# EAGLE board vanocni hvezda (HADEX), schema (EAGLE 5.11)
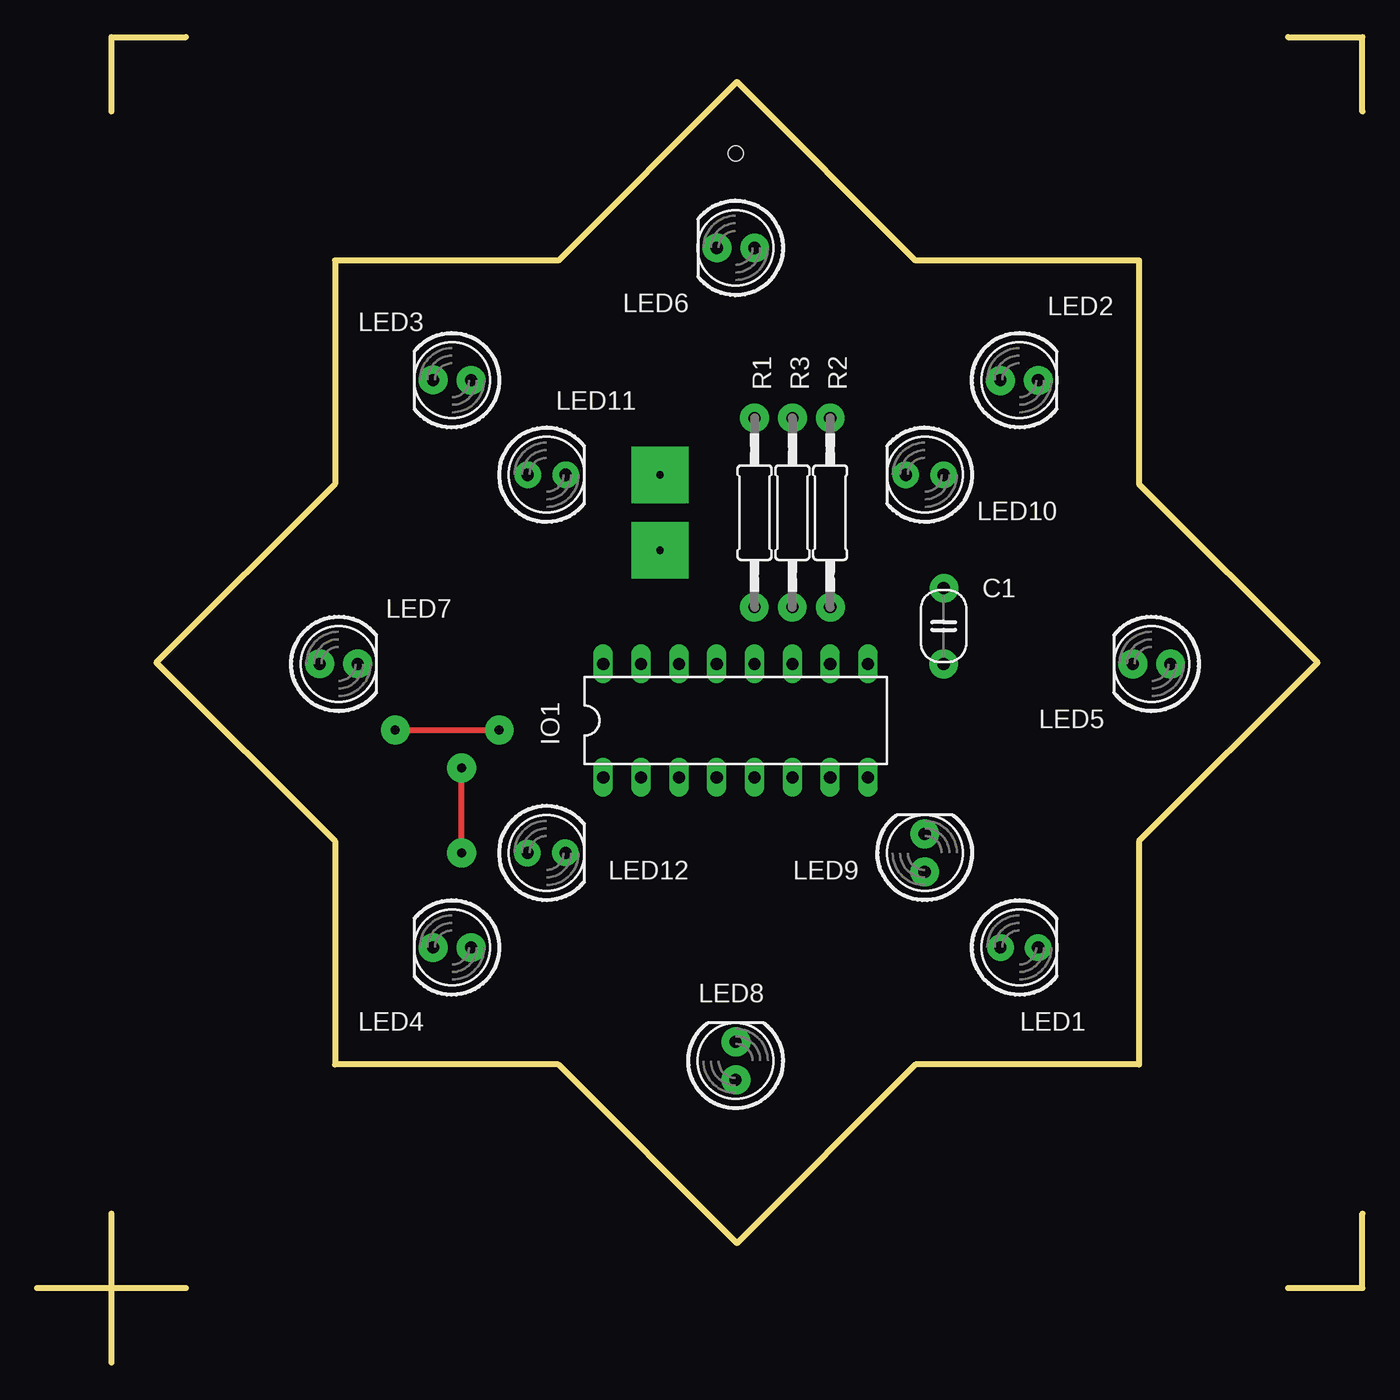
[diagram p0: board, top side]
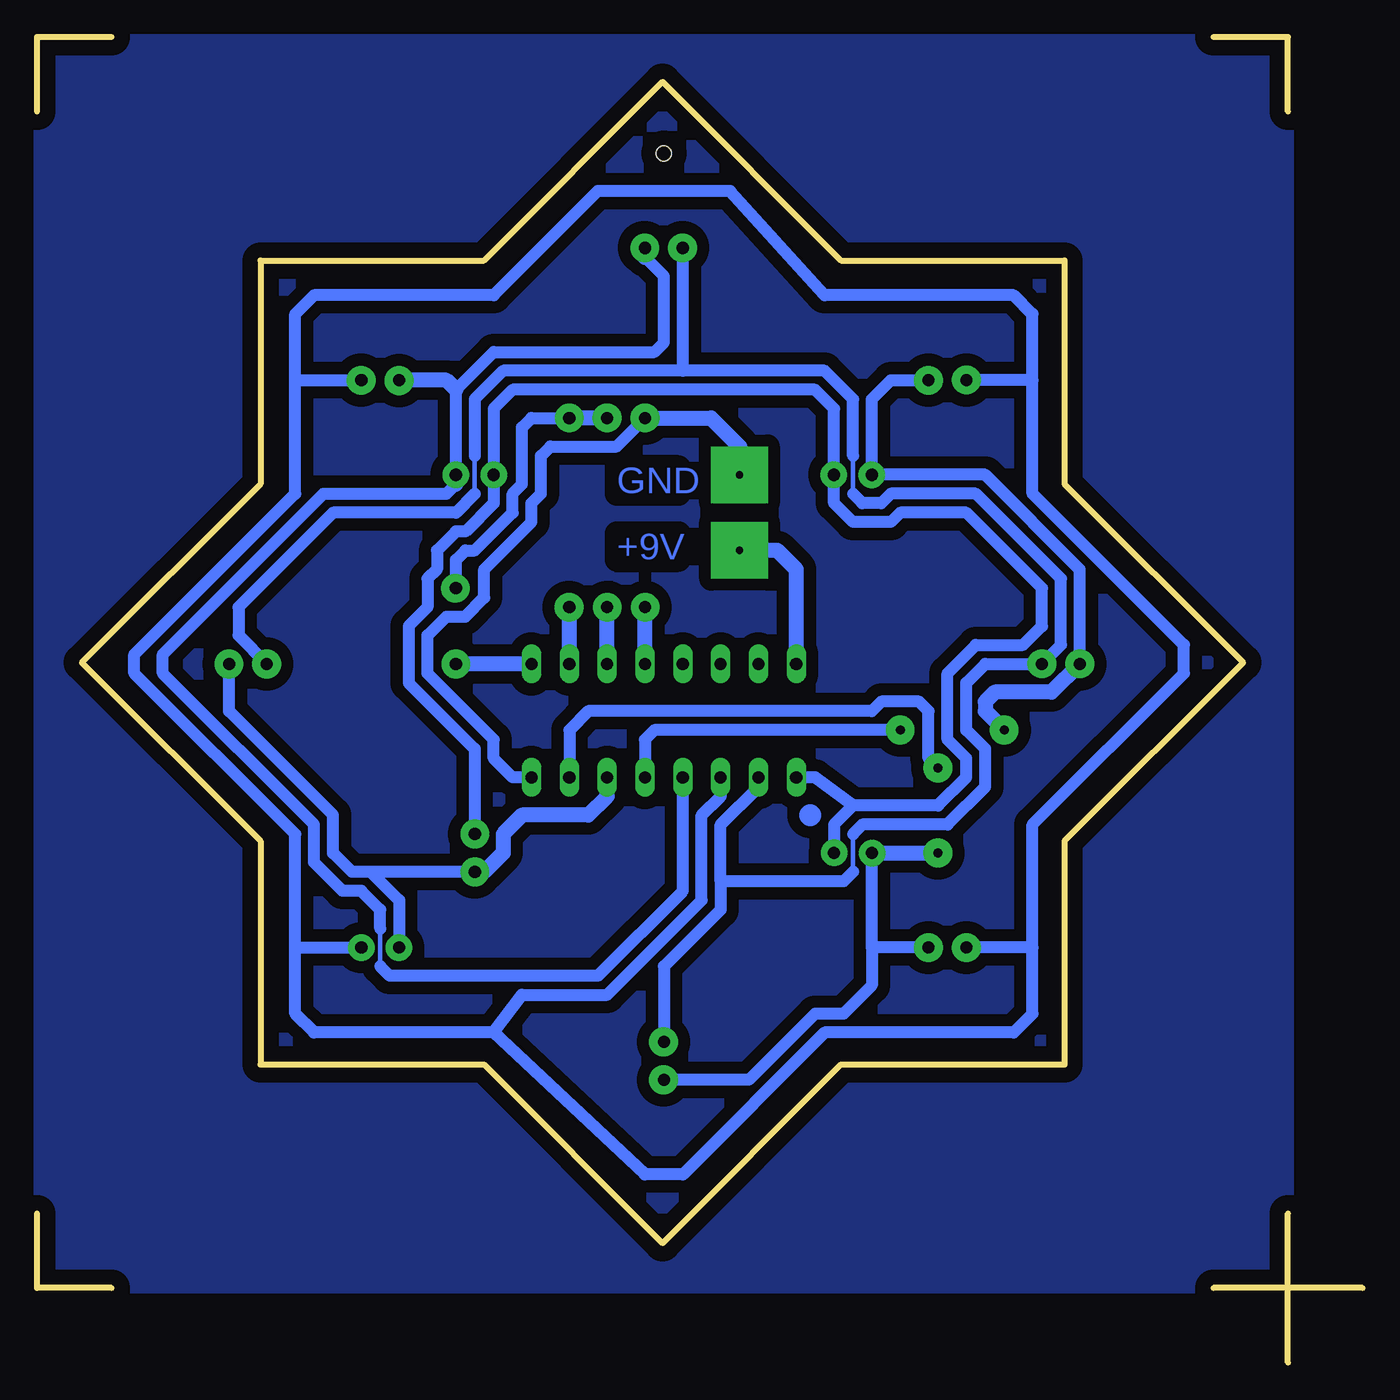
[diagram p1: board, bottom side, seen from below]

Size 89 x 89 mm. Coordinates in mm from the lower left corner, seen from the top.
Outline: 0,5 10,5
Outline: 5,0 5,10
Outline: 10,89 5,89 5,84
Outline: 84,89 89,89 89,84
Outline: 89,10 89,5 84,5
Outline: 59,20 47,8 35,20 20,20 20,35 8,47 20,59 20,74 35,74 47,86 59,74 74,74 74,59 86,47 74,35 74,20 59,20
Copper layers (1*16): Top 0.035mm / dielectric 1.5mm / Bottom 0.035mm
Design rules "default": minimum track width 10mil, minimum drill 24mil, track to track 8mil, track to pad 8mil, pad to pad 8mil, via to via 8mil, smd to smd 8mil, copper to edge 40mil, drill to drill 8mil, minimum pad ring 10mil, minimum via ring 8mil, stop-mask expansion 4mil, vias tented up to drill 0mil, thermal gap 10mil
Holes 1 mm at 46.91,81.2

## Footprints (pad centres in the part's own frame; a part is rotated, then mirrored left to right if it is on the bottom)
C3X5 = drill 0.813 pad 1.422 octagon: 1 -2.54,0; 2 2.54,0
DIL16 = drill 0.813 long: 1 -8.89,-3.81; 2 -6.35,-3.81; 3 -3.81,-3.81; 4 -1.27,-3.81; 5 1.27,-3.81; 6 3.81,-3.81; 7 6.35,-3.81; 8 8.89,-3.81; 9 8.89,3.81; 10 6.35,3.81; 11 3.81,3.81; 12 1.27,3.81; 13 -1.27,3.81; 14 -3.81,3.81; 15 -6.35,3.81; 16 -8.89,3.81
LED5MM = drill 0.813 octagon: A -1.27,0; K 1.27,0
0207/12 = drill 0.813 octagon: 1 -6.35,0; 2 6.35,0

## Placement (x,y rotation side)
C1  [C3X5]  60.88,49.45 90 top
IO1  [DIL16]  46.91,43.1 0 top
LED1  [LED5MM]  65.96,27.86 0 top
LED2  [LED5MM]  65.96,65.96 0 top
LED3  [LED5MM]  27.86,65.96 180 top
LED4  [LED5MM]  27.86,27.86 180 top
LED5  [LED5MM]  74.85,46.91 180 top
LED6  [LED5MM]  46.91,74.85 180 top
LED7  [LED5MM]  20.24,46.91 0 top
LED8  [LED5MM]  46.91,20.24 90 top
LED9  [LED5MM]  59.61,34.21 90 top
LED10  [LED5MM]  59.61,59.61 180 top
LED11  [LED5MM]  34.21,59.61 0 top
LED12  [LED5MM]  34.21,34.21 0 top
R1  [0207/12]  48.18,57.07 90 top
R2  [0207/12]  53.26,57.07 90 top
R3  [0207/12]  50.72,57.07 90 top

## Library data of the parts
C1 = kondenzatory
IO1 = 40xx
LED1-LED12 = LED diody
R1-R3 = rezistory

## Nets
S$1: LED3.A LED7.A LED11.A
S$4: IO1.12 R1.1
S$5: IO1.11 R3.1
S$6: IO1.10 R2.1
S$7: C1.1 IO1.9
S$8: IO1.16
S$9: LED2.A LED6.A LED10.A
S$10: IO1.5
S$13: IO1.7 LED4.A LED8.A LED12.A
S$14: IO1.3 LED1.K LED2.K LED3.K LED4.K
S$17: LED1.A LED5.A LED9.A
S$19: IO1.8 R1.2
S$21: LED5.K LED6.K LED7.K LED8.K
S$22: R2.2 R3.2
S$23: IO1.1 LED9.K LED10.K LED11.K LED12.K
S$24: C1.2

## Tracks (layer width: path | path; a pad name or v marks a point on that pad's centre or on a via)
S$1  (via drill 0.6 pad 1.93)
  Top 0.406: v24.05,42.47 v31.04,42.47
  Bottom 0.813: LED3.A 31.67,65.96 32.94,64.69 LED11.A 25.32,59.61 18.97,53.26 LED7.A
  Bottom 1.016: LED7.A 20.88,45.01 24.68,45.01 25.32,44.37 25.32,43.73 v24.05,42.47
S$2
  Bottom 0.813: 45.64,38.66 45.64,31.67 51.35,25.95 65.33,25.95 65.96,26.59
S$3  (via drill 0.5 pad 1.93)
  other vias: 48.17,50.71
S$4
  Bottom 1.016: IO1.12 R1.1
S$5
  Bottom 1.016: IO1.11 R3.1
S$6
  Bottom 1.016: IO1.10 R2.1
S$7
  Bottom 1.016: IO1.9 C1.1
S$8  (via drill 0.5 pad 3.81)
  Bottom 1.016: IO1.16 38.02,53.26 39.29,54.53 v41.83,54.53
S$9
  Bottom 0.305: 65.96,26.59 65.96,29.13
  Bottom 0.813: 48.18,74.22 46.91,72.94 46.91,68.5 47.55,67.87 58.34,67.87 60.88,65.33 LED10.A | 60.88,58.98 61.52,58.34 69.77,58.34 80.56,47.55 80.56,46.27 70.41,36.11 70.41,33.58 68.5,31.67 67.23,31.67 65.96,30.4 65.96,29.13
  Bottom 1.016: 48.18,74.22 LED6.A | LED2.A 61.52,65.96 60.88,65.33 | 60.88,58.98 LED10.A
S$10
  Bottom 0.813: IO1.5 48.18,41.83 47.55,42.47 31.04,42.47
S$11  (via drill 0.5 pad 1.93)
  other vias: 50.71,50.71
S$13  (via drill 0.6 pad 1.93)
  Top 0.406: v28.5,34.21 v28.5,39.92
  Bottom 0.813: IO1.7 53.26,42.47 51.99,43.73 32.94,43.73 32.3,44.37 29.77,44.37 29.13,43.73 29.13,40.56 v28.5,39.92 | LED8.A 41.2,18.97 36.75,23.41 34.84,23.41 32.94,25.32 32.94,27.86 | 32.94,27.86 LED12.A | LED4.A 32.94,27.86
  Bottom 1.016: LED12.A v28.5,34.21
S$14
  Bottom 0.813: IO1.3 43.1,38.02 44.37,36.75 44.37,31.04 50.72,24.68 56.44,24.68 58.34,22.14 | 22.14,27.86 22.14,23.41 23.41,22.14 36.11,22.14 45.64,12.62 48.18,12.62 58.34,22.14 | 22.14,27.86 LED4.K | 58.34,22.14 70.41,22.14 71.67,23.41 71.67,27.86 | 71.67,27.86 LED1.K | 71.67,27.86 71.67,35.48 82.47,46.27 82.47,47.55 71.67,58.34 71.67,65.96 | 71.67,65.96 LED2.K | 71.67,65.96 71.67,70.41 70.41,71.67 58.34,71.67 51.35,78.66 42.47,78.66 36.11,71.67 23.41,71.67 22.14,70.41 22.14,65.96 | 22.14,65.96 22.14,58.34 11.98,48.18 11.98,46.27 22.14,36.11 22.14,27.86 | 22.14,65.96 LED3.K
S$15  (via drill 0.5 pad 1.93)
  other vias: 53.29,50.71
S$16  (via drill 0.5 pad 1.93)
  other vias: 60.88,46.9
S$17
  Bottom 0.813: LED5.A 76.12,43.73 69.14,36.75 69.14,34.21 67.87,32.94 66.59,32.94 | 66.59,32.94 LED9.A 58.98,32.94 | LED1.A 64.69,31.04 66.59,32.94
  Bottom 1.016: 58.98,32.94 57.7,34.21 57.7,35.48 56.44,36.75 51.99,36.75 50.72,38.02 50.72,38.66
S$18
  pour Bottom (isolate 0.813): 5,5 88.82,5 88.82,88.82 5,88.82
S$19  (via drill 0.5 pad 3.81)
  Bottom 0.813: IO1.8 57.07,39.29 58.34,40.56 58.34,41.83 62.78,46.27 62.78,48.81 61.52,50.09 60.24,50.09 58.98,51.35 58.98,53.26 55.8,56.44 55.8,57.7 55.16,58.34 55.16,60.88 54.53,61.52 50.09,61.52 R1.2
  Bottom 1.016: R1.2 43.73,63.42 41.83,61.52 v41.83,59.61
S$20  (via drill 0.5 pad 1.93)
  other vias: 60.92,51.98
S$21
  Bottom 0.305: 59.61,60.88 59.61,58.34 | 34.21,58.34 34.21,60.88 | 34.21,35.48 34.21,32.94
  Bottom 0.813: LED5.K 75.48,48.81 75.48,50.72 69.14,57.07 60.88,57.07 59.61,58.34 | 59.61,60.88 59.61,64.69 57.7,66.59 45.64,66.59 | 45.64,66.59 LED6.K | 45.64,66.59 36.11,66.59 34.21,64.69 34.21,60.88 | 34.21,58.34 33.58,57.7 32.3,57.7 31.67,58.34 25.95,58.34 20.24,52.62 20.24,48.18 LED7.K 25.32,46.91 26.59,45.64 26.59,42.47 25.32,41.2 25.32,38.66 27.86,36.11 33.58,36.11 34.21,35.48 | LED8.K 46.91,26.59 43.1,30.4 43.1,32.3 | 40.56,38.66 43.1,36.11 43.1,32.3 | 43.1,32.3 34.84,32.3 34.21,32.94
S$22
  Bottom 1.016: R3.2 R2.2
S$23
  Bottom 0.813: LED9.K 59.61,41.2 64.06,45.64 64.06,49.45 62.78,50.72 62.78,52.62 62.15,53.26 62.15,54.53 60.88,55.8 60.24,55.8 58.34,57.7 LED10.K 58.34,64.06 57.07,65.33 36.75,65.33 35.48,64.06 LED11.K 35.48,57.7 34.21,56.44 31.67,56.44 31.04,57.07 26.59,57.07 21.51,51.99 21.51,49.45 22.78,48.18 25.95,48.18 27.86,46.27 27.86,41.83 26.59,40.56 26.59,39.29 28.5,37.38 34.21,37.38 | IO1.1 36.75,39.29 34.21,37.38 | LED12.K 35.48,36.11 34.21,37.38
S$24
  Bottom 0.813: 53.9,63.42 55.8,63.42 56.44,62.78 56.44,58.98 57.07,58.34 57.07,57.07 59.61,54.53 60.24,54.53 60.88,53.9 C1.2
S$25  (via drill 0.5 pad 1.93)
  other vias: 59.61,35.48
S$26  (via drill 0.5 pad 1.93)
  other vias: 59.61,32.94
S$27  (via drill 0.6 pad 1.78)
  other vias: 64.73,27.85
S$28  (via drill 0.6 pad 1.78)
  other vias: 67.24,27.85
S$29  (via drill 0.6 pad 1.78)
  other vias: 58.34,59.62
S$30  (via drill 0.6 pad 1.78)
  other vias: 60.88,59.62
S$31  (via drill 0.6 pad 1.78)
  other vias: 35.5,59.62
S$32  (via drill 0.6 pad 1.78)
  other vias: 32.96,59.62
S$33  (via drill 0.6 pad 1.78)
  other vias: 32.93,34.21
S$34  (via drill 0.6 pad 1.78)
  other vias: 35.48,34.22
S$35  (via drill 0.6 pad 1.93)
  other vias: 67.24,65.95
S$36  (via drill 0.6 pad 1.93)
  other vias: 64.69,65.93
S$37  (via drill 0.6 pad 1.93)
  other vias: 53.27,63.43
S$38  (via drill 0.6 pad 1.93)
  other vias: 50.72,63.43
S$39  (via drill 0.6 pad 1.93)
  other vias: 48.17,63.43
S$40  (via drill 0.6 pad 1.93)
  other vias: 45.65,74.86
S$41  (via drill 0.6 pad 1.93)
  other vias: 48.2,74.86
S$42  (via drill 0.6 pad 1.93)
  other vias: 29.13,65.95
S$43  (via drill 0.6 pad 1.93)
  other vias: 26.59,65.98
S$44  (via drill 0.6 pad 1.93)
  other vias: 18.97,46.91
S$45  (via drill 0.6 pad 1.93)
  other vias: 21.52,46.91
S$46  (via drill 0.6 pad 1.93)
  other vias: 26.59,27.85
S$47  (via drill 0.6 pad 1.93)
  other vias: 29.13,27.85
S$48  (via drill 0.6 pad 1.93)
  other vias: 46.94,21.52
S$49  (via drill 0.6 pad 1.93)
  other vias: 46.94,18.97
S$50  (via drill 0.6 pad 1.93)
  other vias: 73.59,46.89
S$51  (via drill 0.6 pad 1.93)
  other vias: 76.12,46.9
(copper drawn outside any net)
  shapes: Bottom circle x1

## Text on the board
Bottom: GND | +9V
